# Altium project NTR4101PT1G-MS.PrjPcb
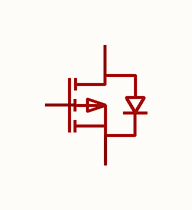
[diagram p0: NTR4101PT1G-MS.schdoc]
1 sheet, 1 parts. Net scope: global (net labels, ports and power ports of the same name join across sheets).

## Sheet NTR4101PT1G-MS.schdoc
size 127 x 101 mm

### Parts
Q?  ntr4101pt1g-ms  [SOT-23-3_L2.9-W1.3-P1.90-LS2.4-BR]  (value not drawn)

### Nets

Not connected (* = marked no-connect by the designer): Q? 1(G) 2(S) 3(D)

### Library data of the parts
Q? = ntr4101pt1g-ms: 数量:1个P沟道;漏源电压(Vdss):20V;连续漏极电流(Id):3.2A;导通电阻(RDS(on)):70mΩ@4.5V；90mΩ@2.5V;耗散功率(Pd):1.56W;阈值电压(Vgs(th)):700mV@250uA;; Manufacturer: MSKSEMI(美森科); AddInBom: yes; ModelId: c62791f0466c4ae2a892c056b845b0ca; ModelName: SOT-23-3P_L2.9-W1.3-H1.0-LS2.4-P0.95; ModelTransform: 98.425,114.173,0,180,0,0,0.0005,-0.0005,0; Number: 1个P沟道; Drain to Source Voltage: 20V; Current - Continuous Drain(Id): 3.2A; Pd - Power Dissipation: 1.56W; Gate Charge(Qg): 4.8nC@4.5V; Input Capacitance(Ciss): 550pF; Reverse Transfer Capacitance (Crss@Vds): 55pF; Type: P沟道; Output Capacitance(Coss): 65pF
